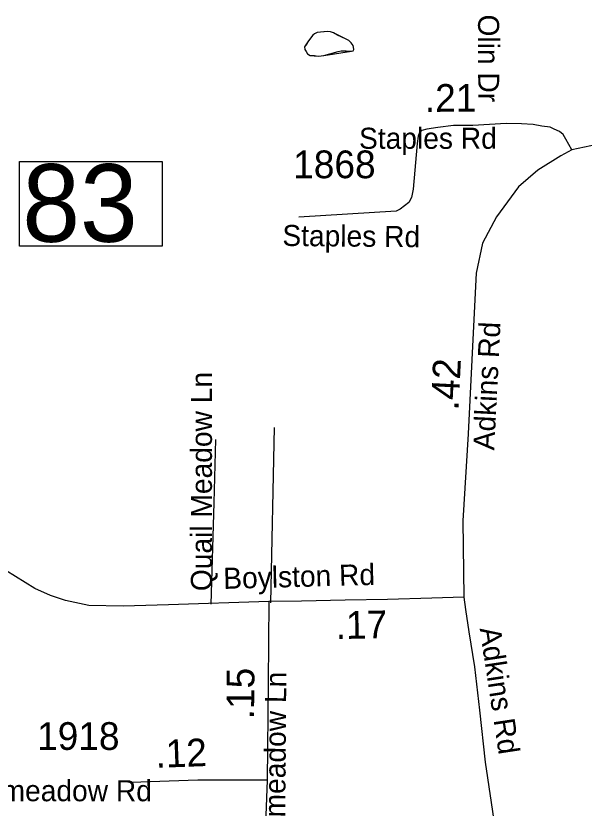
# Model space of a CAD drawing. Extents: x 1662474 to 1856135, y 779280 to 917889.
# Drawn here: x 1699328 to 1701892, y 848796 to 852368 of the extents above; entities that cross this region are included whole.
import ezdxf

# ---------------------------------------------------------------- set-up
doc = ezdxf.new("R2010")
doc.units = 0
for name, color, linetype in [('Exist Hydrographic Misc Water Feature', 7, 'Continuous'), ('Exist Road Non-System Type 51', 7, 'Continuous'), ('Exist Road Non-System Type 51 Label', 7, 'Continuous'), ('Exist Road Secondary Mileage Hundredths English Label', 7, 'Continuous'), ('Exist Road Secondary Mileage Tenths English Label', 7, 'Continuous'), ('Exist Road Secondary Structure Standard Bridge Number Label', 7, 'Continuous'), ('Exist Road Secondary Type 51 Attributed', 7, 'Continuous'), ('Exist Road Secondary Type 51 Label', 7, 'Continuous'), ('Exist Road Secondary Type 51 Number Label', 7, 'Continuous')]:
    doc.layers.add(name, color=color, linetype=linetype)

msp = doc.modelspace()

# ---------------------------------------------------------------- linework, layer by layer
at = {"layer": 'Exist Hydrographic Misc Water Feature'}
for points in [[(1700649.1, 852255.6), (1700641, 852241.8), (1700634.6, 852233.8), (1700630.6, 852228.1), (1700632.5, 852215.8), (1700637.8, 852206.7), (1700644.3, 852197.4), (1700655.8, 852189), (1700675.9, 852189.4), (1700691.9, 852186.6), (1700705.4, 852187.2), (1700718.1, 852188.6), (1700782.5, 852207), (1700796.5, 852210.8), (1700818.4, 852211.1), (1700832.5, 852208.4), (1700842.6, 852208.2), (1700849.7, 852210.5), (1700852.6, 852216.2), (1700852.4, 852226.9), (1700850.8, 852234.2), (1700841.1, 852246.7), (1700831, 852256.8), (1700819.3, 852262.8), (1700779.6, 852281.7), (1700761.3, 852291.9), (1700748.6, 852296.3), (1700734, 852298.2), (1700717.8, 852296.1), (1700687.7, 852292.6), (1700675.4, 852287.1), (1700667.6, 852281.5), (1700649.1, 852255.6)], [(1700649.1, 852255.6), (1700630.6, 852228.1), (1700632.5, 852215.8), (1700637.8, 852206.7), (1700644.3, 852197.4), (1700655.8, 852189), (1700691.9, 852186.6), (1700705.4, 852187.2), (1700718.1, 852188.6), (1700842.6, 852208.2), (1700849.7, 852210.5), (1700852.6, 852216.2), (1700852.4, 852226.9), (1700850.8, 852234.2), (1700841.1, 852246.7), (1700831, 852256.8), (1700819.3, 852262.8), (1700761.3, 852291.9), (1700748.6, 852296.3), (1700734, 852298.2), (1700687.7, 852292.6), (1700675.4, 852287.1), (1700667.6, 852281.5), (1700649.1, 852255.6)]]:
    msp.add_lwpolyline(points, dxfattribs=at)
at = {"layer": 'Exist Road Non-System Type 51'}
msp.add_line((1700493.9, 850511.9), (1700477.1, 849722.1), dxfattribs=at)
for points in [[(1701043.8, 851487.6), (1700604.4, 851459.9)], [(1700210.1, 849714.8), (1700222.9, 850172.5), (1700230.1, 850458.4)]]:
    msp.add_lwpolyline(points, dxfattribs=at)
at = {"layer": 'Exist Road Secondary Structure Standard Bridge Number Label'}
msp.add_lwpolyline([(1699345.1, 851711.9), (1699989.2, 851711.9), (1699989.2, 851329.6), (1699345.1, 851329.6)], close=True, dxfattribs=at)
at = {"layer": 'Exist Road Secondary Type 51 Attributed'}
for points in [[(1701836.6, 851764.2), (1701809.6, 851812.8), (1701798, 851833), (1701780.3, 851847.4), (1701756.5, 851857.8), (1701738.6, 851866.2), (1701700.7, 851871), (1701662.8, 851877.8), (1701608.9, 851880.9), (1701540.9, 851882.2), (1701390.6, 851873.3), (1701302.5, 851873), (1701232.3, 851864.5), (1701182.1, 851857.5), (1701160, 851851.9), (1701149.8, 851842.1), (1701143.5, 851826.2), (1701138.8, 851792.3), (1701120.6, 851586.6), (1701113.8, 851548.7), (1701101.4, 851526.9), (1701062.7, 851495.7), (1701043.8, 851487.6)], [(1703854.9, 851871.7), (1703813.1, 851826.2), (1703786.8, 851812.7), (1703734.7, 851809.8), (1703636.7, 851809.8), (1703496.5, 851804.6), (1703334.5, 851807.9), (1703148.3, 851805.6), (1702938.1, 851803.9), (1702692, 851806.9), (1702455.7, 851799.7), (1702235.6, 851800.1), (1702065.4, 851793.6), (1701951.2, 851787.9), (1701836.6, 851764.2)], [(1701836.6, 851764.2), (1701787.2, 851736.5), (1701683.7, 851672.8), (1701596.1, 851597.2), (1701496.6, 851461.9), (1701432.9, 851342.5), (1701405, 851207.2), (1701393.1, 850968.4), (1701369.2, 850482.9), (1701345.3, 850091.4), (1701350.1, 849746.6)], [(1700469.5, 849728), (1700017.5, 849711.7), (1699813, 849706.5), (1699657.6, 849709), (1699551.9, 849732.5), (1699484.8, 849754.1), (1699414.6, 849786.7), (1699238.8, 849894), (1698898.4, 850176), (1698429.8, 850539), (1698385.5, 850570.1), (1698337.3, 850594.7), (1698259.9, 850612.6), (1698204.5, 850618.5), (1698098.5, 850620.2)], [(1701350.1, 849746.6), (1701205.3, 849742.8), (1701004.6, 849736.5), (1700814.5, 849732.8), (1700617.1, 849729.1), (1700469.5, 849728)], [(1701350.1, 849746.6), (1701356.5, 849691.5), (1701372.3, 849590.5), (1701397.6, 849432.7), (1701419.7, 849236.9), (1701445, 849003.3), (1701489.2, 848709.7), (1701513.4, 848553.1), (1701566.3, 848204.1), (1701602.9, 847935.2), (1701617.4, 847783)], [(1700469.5, 849728), (1700467.1, 849361.2), (1700462.3, 848921.5)], [(1700462.3, 848921.5), (1700149.1, 848921.5), (1699849.3, 848910.5)], [(1700462.3, 848921.5), (1700450.1, 848602.6), (1700434.2, 848491.5), (1700402.4, 848408.1), (1700346.8, 848320.8), (1700184, 848142.2), (1699850.4, 847812.7)]]:
    msp.add_lwpolyline(points, dxfattribs=at)

# ---------------------------------------------------------------- texts
at = {"layer": 'Exist Road Non-System Type 51 Label'}
for s, rotation, p in [('Olin Dr', 270.0775, (1701413.7, 852374.1)), ('Staples Rd', 359.4586, (1700530.5, 851330.6)), ('Quail Meadow Ln', 90, (1700213.2, 849774))]:
    msp.add_text(s, height=95, rotation=rotation, dxfattribs=at).set_placement(p)
at = {"layer": 'Exist Road Secondary Mileage Hundredths English Label'}
for s, rotation, p in [('.21', 0.1942, (1701173.8, 851935.1)), ('.15', 89.3834, (1700402.8, 849195.6)), ('.12', 2.0949, (1699960.2, 848977.1))]:
    msp.add_text(s, height=125, rotation=rotation, dxfattribs=at).set_placement(p)
at = {"layer": 'Exist Road Secondary Mileage Tenths English Label'}
for s, rotation, p in [('.42', 87.1834, (1701325.1, 850587.7)), ('.17', 1.1014, (1700772.4, 849557.7))]:
    msp.add_text(s, height=125, rotation=rotation, dxfattribs=at).set_placement(p)
at = {"layer": 'Exist Road Secondary Structure Standard Bridge Number Label'}
msp.add_text('83', height=350, dxfattribs=at).set_placement((1699357.6, 851349.4))
at = {"layer": 'Exist Road Secondary Type 51 Label'}
for s, p in [('Staples Rd', (1700876.7, 851768.6)), ('Sweetmeadow Rd', (1698911.2, 848826.7))]:
    msp.add_text(s, height=95, dxfattribs=at).set_placement(p)
for s, rotation, p in [('Adkins Rd', 87.1849, (1701486.6, 850407.9)), ('Boylston Rd', 1.5426, (1700265.4, 849783.9)), ('Adkins Rd', 278.6388, (1701420.6, 849605.4)), ('Quailmeadow Ln', 89.5481, (1700541.3, 848456.9))]:
    msp.add_text(s, height=95, rotation=rotation, dxfattribs=at).set_placement(p)
at = {"layer": 'Exist Road Secondary Type 51 Number Label'}
for s, p in [('1868', (1700579.6, 851636)), ('1918', (1699424.4, 849058.2))]:
    msp.add_text(s, height=125, dxfattribs=at).set_placement(p)

doc.saveas('drawing.dxf')
